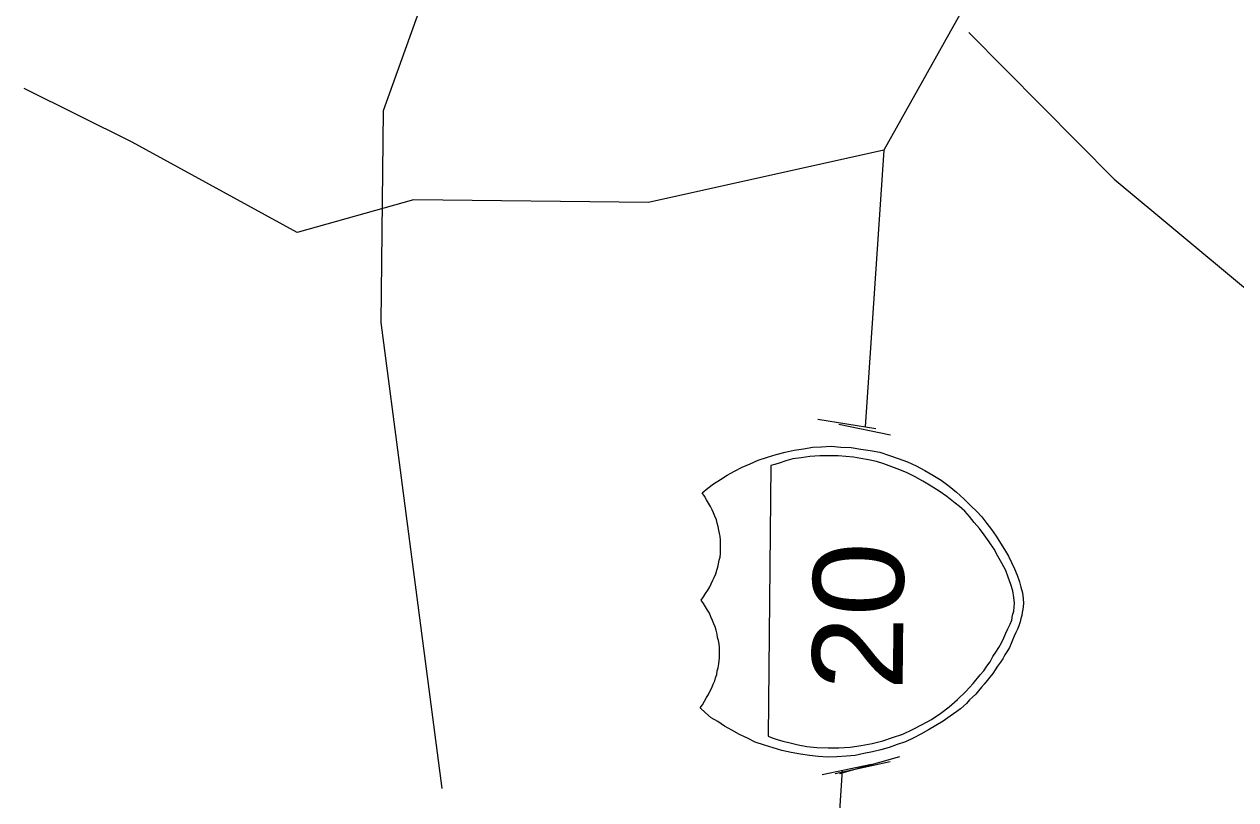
# Model space of a CAD drawing. Extents: x 2356576 to 2377878, y 6966390 to 6990634.
# Drawn here: x 2365922.2 to 2366013.1, y 6968773.4 to 6968831.6 of the extents above; entities that cross this region are included whole.
import ezdxf

# ---------------------------------------------------------------- set-up
doc = ezdxf.new("R2010")
doc.units = 0
doc.header["$LTSCALE"] = 7.1
doc.layers.add('19', color=7, linetype='Continuous', lineweight=13)
doc.layers.add('8', color=7, linetype='Continuous', lineweight=13)

msp = doc.modelspace()

# ---------------------------------------------------------------- linework, layer by layer
at = {"layer": '19', "lineweight": 25}
for p, q in [((2365930.315, 6968822.751), (2365922.224, 6968826.795)), ((2365986.716, 6968822.166), (2365985.329, 6968801.392))]:
    msp.add_line(p, q, dxfattribs=at)
at = {"layer": '19'}
for p, q in [((2365981.766, 6968801.969), (2365986.107, 6968801.264)), ((2365983.351, 6968801.592), (2365987.215, 6968800.8)), ((2365983.079, 6968775.402), (2365987.201, 6968776.287)), ((2365983.411, 6968775.398), (2365987.925, 6968776.671)), ((2365982.09, 6968775.32), (2365985.787, 6968776.094))]:
    msp.add_line(p, q, dxfattribs=at)
at = {"layer": '19', "lineweight": 25}
for points in [[(2365993.212, 6969055.404), (2365995.144, 6969044.943), (2365996.174, 6969031.612), (2365997.392, 6969012.874), (2365997.254, 6968999.555), (2365998.323, 6968990.003), (2366002.006, 6968983.305), (2366004.476, 6968969.926), (2366002.874, 6968951.222), (2366001.496, 6968934.107), (2366000.162, 6968915.368), (2366003.604, 6968885.811), (2365999.567, 6968857.919), (2365994.142, 6968835.442), (2365986.716, 6968822.166), (2365969.062, 6968818.241), (2365951.423, 6968818.424), (2365942.698, 6968815.994), (2365930.315, 6968822.751)], [(2365952.596, 6968844.725), (2365953.012, 6968835.868), (2365949.152, 6968825.108), (2365948.988, 6968809.237), (2365953.546, 6968774.267)], [(2365983.594, 6968775.636), (2365982.344, 6968756.568), (2365971.97, 6968737.143), (2365955.574, 6968726.78)]]:
    msp.add_lwpolyline(points, dxfattribs=at)
at = {"layer": '19'}
for points in [[(2365993.108, 6968830.981), (2366004.002, 6968819.979), (2366013.699, 6968811.898), (2366030.324, 6968794.501), (2366048.07, 6968778.809)], [(2365973.652, 6968789.388), (2365973.774, 6968789.627), (2365973.897, 6968789.897), (2365973.991, 6968790.105), (2365974.114, 6968790.375), (2365974.177, 6968790.643), (2365974.267, 6968790.882), (2365974.302, 6968791.121), (2365974.364, 6968791.393), (2365974.427, 6968791.632), (2365974.458, 6968791.9), (2365974.46, 6968792.14), (2365974.463, 6968792.412), (2365974.466, 6968792.652), (2365974.468, 6968792.892), (2365974.443, 6968793.192), (2365974.385, 6968793.401), (2365974.328, 6968793.641), (2365974.299, 6968793.914), (2365974.213, 6968794.182), (2365974.156, 6968794.423), (2365974.039, 6968794.696), (2365973.949, 6968794.937), (2365973.832, 6968795.178), (2365973.714, 6968795.42), (2365973.569, 6968795.661), (2365973.419, 6968795.935), (2365973.274, 6968796.204), (2365973.097, 6968796.446), (2365973.52, 6968796.802), (2365973.944, 6968797.129), (2365974.455, 6968797.452), (2365974.971, 6968797.779), (2365975.514, 6968798.073), (2365976.089, 6968798.367), (2365976.692, 6968798.629), (2365977.294, 6968798.895), (2365977.985, 6968799.128), (2365978.647, 6968799.329), (2365979.309, 6968799.502), (2365980.002, 6968799.647), (2365980.691, 6968799.76), (2365981.385, 6968799.872), (2365982.045, 6968799.894), (2365982.766, 6968799.946), (2365983.485, 6968799.879), (2365984.265, 6968799.843), (2365984.983, 6968799.715), (2365985.702, 6968799.616), (2365986.421, 6968799.488), (2365987.138, 6968799.241), (2365987.796, 6968799.026), (2365988.482, 6968798.779), (2365989.139, 6968798.472), (2365989.795, 6968798.133), (2365990.391, 6968797.767), (2365991.02, 6968797.401), (2365991.615, 6968796.946), (2365992.178, 6968796.488), (2365992.713, 6968796.003), (2365993.28, 6968795.457), (2365993.664, 6968795.061), (2365994.079, 6968794.637), (2365994.434, 6968794.153), (2365994.789, 6968793.701), (2365995.144, 6968793.186), (2365995.471, 6968792.674), (2365995.766, 6968792.191), (2365996.061, 6968791.708), (2365996.296, 6968791.226), (2365996.531, 6968790.743), (2365996.734, 6968790.261), (2365996.909, 6968789.779), (2365996.997, 6968789.358), (2365997.112, 6968788.937), (2365997.168, 6968788.516), (2365997.192, 6968788.156)], [(2365997.192, 6968788.156), (2365997.162, 6968787.916), (2365997.159, 6968787.704), (2365997.097, 6968787.465), (2365997.063, 6968787.257), (2365997, 6968787.018), (2365996.938, 6968786.779), (2365996.847, 6968786.48), (2365996.752, 6968786.209), (2365996.629, 6968785.97), (2365996.507, 6968785.703), (2365996.384, 6968785.404), (2365996.261, 6968785.134), (2365996.138, 6968784.835), (2365995.987, 6968784.596), (2365995.804, 6968784.298), (2365995.649, 6968784), (2365995.466, 6968783.734), (2365995.255, 6968783.436), (2365995.072, 6968783.166), (2365994.89, 6968782.9), (2365994.675, 6968782.63), (2365994.464, 6968782.364), (2365994.249, 6968782.094), (2365994.039, 6968781.856), (2365993.824, 6968781.591), (2365993.614, 6968781.353), (2365993.371, 6968781.115), (2365993.157, 6968780.905), (2365992.914, 6968780.64), (2365992.704, 6968780.43), (2365992.462, 6968780.253), (2365992.188, 6968780.047), (2365991.704, 6968779.692), (2365991.16, 6968779.306), (2365990.617, 6968778.984), (2365990.073, 6968778.657), (2365989.502, 6968778.335), (2365988.927, 6968778.041), (2365988.356, 6968777.775), (2365987.722, 6968777.574), (2365987.12, 6968777.34), (2365986.49, 6968777.166), (2365985.856, 6968777.021), (2365985.227, 6968776.879), (2365984.565, 6968776.734), (2365983.905, 6968776.681), (2365983.184, 6968776.629), (2365982.524, 6968776.607), (2365981.804, 6968776.675), (2365981.145, 6968776.742), (2365980.454, 6968776.837), (2365979.767, 6968776.964), (2365979.077, 6968777.123), (2365978.419, 6968777.31), (2365977.761, 6968777.525), (2365977.075, 6968777.744), (2365976.478, 6968778.05), (2365975.881, 6968778.324), (2365975.312, 6968778.63), (2365974.775, 6968778.936), (2365974.267, 6968779.301), (2365973.762, 6968779.578), (2365973.346, 6968779.943), (2365972.93, 6968780.307), (2365973.112, 6968780.545), (2365973.263, 6968780.812), (2365973.418, 6968781.082), (2365973.568, 6968781.32), (2365973.691, 6968781.587), (2365973.813, 6968781.826), (2365973.908, 6968782.097), (2365974.031, 6968782.336), (2365974.093, 6968782.575), (2365974.184, 6968782.814), (2365974.218, 6968783.082), (2365974.281, 6968783.321), (2365974.344, 6968783.621), (2365974.374, 6968783.832), (2365974.377, 6968784.072), (2365974.38, 6968784.372), (2365974.382, 6968784.612), (2365974.385, 6968784.852), (2365974.36, 6968785.12), (2365974.302, 6968785.361), (2365974.244, 6968785.602), (2365974.215, 6968785.842), (2365974.13, 6968786.143), (2365974.073, 6968786.383), (2365973.955, 6968786.625), (2365973.866, 6968786.866), (2365973.748, 6968787.139), (2365973.631, 6968787.408), (2365973.486, 6968787.65), (2365973.336, 6968787.891), (2365973.191, 6968788.133), (2365973.013, 6968788.407), (2365973.196, 6968788.645), (2365973.346, 6968788.883), (2365973.501, 6968789.15), (2365973.652, 6968789.388)]]:
    msp.add_lwpolyline(points, dxfattribs=at)
msp.add_lwpolyline([(2365978.25, 6968798.493), (2365978.04, 6968778.182), (2365978.339, 6968778.059), (2365978.725, 6968777.935), (2365979.144, 6968777.81), (2365979.683, 6968777.685), (2365980.281, 6968777.531), (2365980.94, 6968777.404), (2365981.691, 6968777.336), (2365982.531, 6968777.327), (2365983.339, 6968777.319), (2365984.18, 6968777.37), (2365985.021, 6968777.482), (2365985.835, 6968777.653), (2365986.645, 6968777.853), (2365987.367, 6968778.085), (2365988.15, 6968778.349), (2365988.874, 6968778.702), (2365989.597, 6968779.054), (2365990.293, 6968779.435), (2365990.986, 6968779.908), (2365991.623, 6968780.381), (2365992.257, 6968780.947), (2365992.863, 6968781.541), (2365993.41, 6968782.135), (2365993.956, 6968782.789), (2365994.231, 6968783.086), (2365994.443, 6968783.444), (2365994.687, 6968783.77), (2365994.903, 6968784.16), (2365995.114, 6968784.485), (2365995.358, 6968784.843), (2365995.541, 6968785.201), (2365995.725, 6968785.559), (2365995.881, 6968785.918), (2365996.032, 6968786.248), (2365996.188, 6968786.606), (2365996.311, 6968786.905), (2365996.375, 6968787.265), (2365996.466, 6968787.564), (2365996.501, 6968787.863), (2365996.532, 6968788.163), (2365996.477, 6968788.584), (2365996.394, 6968789.092), (2365996.247, 6968789.574), (2365996.044, 6968790.116), (2365995.87, 6968790.63), (2365995.575, 6968791.173), (2365995.281, 6968791.684), (2365994.986, 6968792.227), (2365994.632, 6968792.771), (2365994.245, 6968793.287), (2365993.89, 6968793.771), (2365993.507, 6968794.223), (2365993.152, 6968794.678), (2365992.796, 6968795.07), (2365992.407, 6968795.434), (2365992.082, 6968795.681), (2365991.455, 6968796.168), (2365990.859, 6968796.562), (2365990.263, 6968796.96), (2365989.639, 6968797.327), (2365989.07, 6968797.661), (2365988.473, 6968797.939), (2365987.908, 6968798.185), (2365987.31, 6968798.399), (2365986.712, 6968798.617), (2365986.174, 6968798.803), (2365985.575, 6968798.929), (2365985.004, 6968799.023), (2365984.437, 6968799.121), (2365983.866, 6968799.187), (2365983.298, 6968799.221), (2365982.758, 6968799.226), (2365981.918, 6968799.235), (2365981.166, 6968799.183), (2365980.504, 6968799.07), (2365979.903, 6968798.988), (2365979.362, 6968798.841), (2365978.94, 6968798.698), (2365978.551, 6968798.582)], close=True, dxfattribs=at)
at = {"layer": '8', "lineweight": 25}
for p, q in [((2365930.315, 6968822.751), (2365922.224, 6968826.795)), ((2365986.716, 6968822.166), (2365985.329, 6968801.392))]:
    msp.add_line(p, q, dxfattribs=at)
at = {"layer": '8'}
for p, q in [((2365981.766, 6968801.969), (2365986.107, 6968801.264)), ((2365983.351, 6968801.592), (2365987.215, 6968800.8)), ((2365983.079, 6968775.402), (2365987.201, 6968776.287)), ((2365983.411, 6968775.398), (2365987.925, 6968776.671)), ((2365982.09, 6968775.32), (2365985.787, 6968776.094))]:
    msp.add_line(p, q, dxfattribs=at)
at = {"layer": '8', "lineweight": 25}
for points in [[(2365993.212, 6969055.404), (2365995.144, 6969044.943), (2365996.174, 6969031.612), (2365997.392, 6969012.874), (2365997.254, 6968999.555), (2365998.323, 6968990.003), (2366002.006, 6968983.305), (2366004.476, 6968969.926), (2366002.874, 6968951.222), (2366001.496, 6968934.107), (2366000.162, 6968915.368), (2366003.604, 6968885.811), (2365999.567, 6968857.919), (2365994.142, 6968835.442), (2365986.716, 6968822.166), (2365969.062, 6968818.241), (2365951.423, 6968818.424), (2365942.698, 6968815.994), (2365930.315, 6968822.751)], [(2365952.596, 6968844.725), (2365953.012, 6968835.868), (2365949.152, 6968825.108), (2365948.988, 6968809.237), (2365953.546, 6968774.267)], [(2365983.594, 6968775.636), (2365982.344, 6968756.568), (2365971.97, 6968737.143), (2365955.574, 6968726.78)]]:
    msp.add_lwpolyline(points, dxfattribs=at)
at = {"layer": '8'}
for points in [[(2365993.108, 6968830.981), (2366004.002, 6968819.979), (2366013.699, 6968811.898), (2366030.324, 6968794.501), (2366048.07, 6968778.809)], [(2365973.652, 6968789.388), (2365973.774, 6968789.627), (2365973.897, 6968789.897), (2365973.991, 6968790.105), (2365974.114, 6968790.375), (2365974.177, 6968790.643), (2365974.267, 6968790.882), (2365974.302, 6968791.121), (2365974.364, 6968791.393), (2365974.427, 6968791.632), (2365974.458, 6968791.9), (2365974.46, 6968792.14), (2365974.463, 6968792.412), (2365974.466, 6968792.652), (2365974.468, 6968792.892), (2365974.443, 6968793.192), (2365974.385, 6968793.401), (2365974.328, 6968793.641), (2365974.299, 6968793.914), (2365974.213, 6968794.182), (2365974.156, 6968794.423), (2365974.039, 6968794.696), (2365973.949, 6968794.937), (2365973.832, 6968795.178), (2365973.714, 6968795.42), (2365973.569, 6968795.661), (2365973.419, 6968795.935), (2365973.274, 6968796.204), (2365973.097, 6968796.446), (2365973.52, 6968796.802), (2365973.944, 6968797.129), (2365974.455, 6968797.452), (2365974.971, 6968797.779), (2365975.514, 6968798.073), (2365976.089, 6968798.367), (2365976.692, 6968798.629), (2365977.294, 6968798.895), (2365977.985, 6968799.128), (2365978.647, 6968799.329), (2365979.309, 6968799.502), (2365980.002, 6968799.647), (2365980.691, 6968799.76), (2365981.385, 6968799.872), (2365982.045, 6968799.894), (2365982.766, 6968799.946), (2365983.485, 6968799.879), (2365984.265, 6968799.843), (2365984.983, 6968799.715), (2365985.702, 6968799.616), (2365986.421, 6968799.488), (2365987.138, 6968799.241), (2365987.796, 6968799.026), (2365988.482, 6968798.779), (2365989.139, 6968798.472), (2365989.795, 6968798.133), (2365990.391, 6968797.767), (2365991.02, 6968797.401), (2365991.615, 6968796.946), (2365992.178, 6968796.488), (2365992.713, 6968796.003), (2365993.28, 6968795.457), (2365993.664, 6968795.061), (2365994.079, 6968794.637), (2365994.434, 6968794.153), (2365994.789, 6968793.701), (2365995.144, 6968793.186), (2365995.471, 6968792.674), (2365995.766, 6968792.191), (2365996.061, 6968791.708), (2365996.296, 6968791.226), (2365996.531, 6968790.743), (2365996.734, 6968790.261), (2365996.909, 6968789.779), (2365996.997, 6968789.358), (2365997.112, 6968788.937), (2365997.168, 6968788.516), (2365997.192, 6968788.156)], [(2365997.192, 6968788.156), (2365997.162, 6968787.916), (2365997.159, 6968787.704), (2365997.097, 6968787.465), (2365997.063, 6968787.257), (2365997, 6968787.018), (2365996.938, 6968786.779), (2365996.847, 6968786.48), (2365996.752, 6968786.209), (2365996.629, 6968785.97), (2365996.507, 6968785.703), (2365996.384, 6968785.404), (2365996.261, 6968785.134), (2365996.138, 6968784.835), (2365995.987, 6968784.596), (2365995.804, 6968784.298), (2365995.649, 6968784), (2365995.466, 6968783.734), (2365995.255, 6968783.436), (2365995.072, 6968783.166), (2365994.89, 6968782.9), (2365994.675, 6968782.63), (2365994.464, 6968782.364), (2365994.249, 6968782.094), (2365994.039, 6968781.856), (2365993.824, 6968781.591), (2365993.614, 6968781.353), (2365993.371, 6968781.115), (2365993.157, 6968780.905), (2365992.914, 6968780.64), (2365992.704, 6968780.43), (2365992.462, 6968780.253), (2365992.188, 6968780.047), (2365991.704, 6968779.692), (2365991.16, 6968779.306), (2365990.617, 6968778.984), (2365990.073, 6968778.657), (2365989.502, 6968778.335), (2365988.927, 6968778.041), (2365988.356, 6968777.775), (2365987.722, 6968777.574), (2365987.12, 6968777.34), (2365986.49, 6968777.166), (2365985.856, 6968777.021), (2365985.227, 6968776.879), (2365984.565, 6968776.734), (2365983.905, 6968776.681), (2365983.184, 6968776.629), (2365982.524, 6968776.607), (2365981.804, 6968776.675), (2365981.145, 6968776.742), (2365980.454, 6968776.837), (2365979.767, 6968776.964), (2365979.077, 6968777.123), (2365978.419, 6968777.31), (2365977.761, 6968777.525), (2365977.075, 6968777.744), (2365976.478, 6968778.05), (2365975.881, 6968778.324), (2365975.312, 6968778.63), (2365974.775, 6968778.936), (2365974.267, 6968779.301), (2365973.762, 6968779.578), (2365973.346, 6968779.943), (2365972.93, 6968780.307), (2365973.112, 6968780.545), (2365973.263, 6968780.812), (2365973.418, 6968781.082), (2365973.568, 6968781.32), (2365973.691, 6968781.587), (2365973.813, 6968781.826), (2365973.908, 6968782.097), (2365974.031, 6968782.336), (2365974.093, 6968782.575), (2365974.184, 6968782.814), (2365974.218, 6968783.082), (2365974.281, 6968783.321), (2365974.344, 6968783.621), (2365974.374, 6968783.832), (2365974.377, 6968784.072), (2365974.38, 6968784.372), (2365974.382, 6968784.612), (2365974.385, 6968784.852), (2365974.36, 6968785.12), (2365974.302, 6968785.361), (2365974.244, 6968785.602), (2365974.215, 6968785.842), (2365974.13, 6968786.143), (2365974.073, 6968786.383), (2365973.955, 6968786.625), (2365973.866, 6968786.866), (2365973.748, 6968787.139), (2365973.631, 6968787.408), (2365973.486, 6968787.65), (2365973.336, 6968787.891), (2365973.191, 6968788.133), (2365973.013, 6968788.407), (2365973.196, 6968788.645), (2365973.346, 6968788.883), (2365973.501, 6968789.15), (2365973.652, 6968789.388)]]:
    msp.add_lwpolyline(points, dxfattribs=at)
msp.add_lwpolyline([(2365978.25, 6968798.493), (2365978.04, 6968778.182), (2365978.339, 6968778.059), (2365978.725, 6968777.935), (2365979.144, 6968777.81), (2365979.683, 6968777.685), (2365980.281, 6968777.531), (2365980.94, 6968777.404), (2365981.691, 6968777.336), (2365982.531, 6968777.327), (2365983.339, 6968777.319), (2365984.18, 6968777.37), (2365985.021, 6968777.482), (2365985.835, 6968777.653), (2365986.645, 6968777.853), (2365987.367, 6968778.085), (2365988.15, 6968778.349), (2365988.874, 6968778.702), (2365989.597, 6968779.054), (2365990.293, 6968779.435), (2365990.986, 6968779.908), (2365991.623, 6968780.381), (2365992.257, 6968780.947), (2365992.863, 6968781.541), (2365993.41, 6968782.135), (2365993.956, 6968782.789), (2365994.231, 6968783.086), (2365994.443, 6968783.444), (2365994.687, 6968783.77), (2365994.903, 6968784.16), (2365995.114, 6968784.485), (2365995.358, 6968784.843), (2365995.541, 6968785.201), (2365995.725, 6968785.559), (2365995.881, 6968785.918), (2365996.032, 6968786.248), (2365996.188, 6968786.606), (2365996.311, 6968786.905), (2365996.375, 6968787.265), (2365996.466, 6968787.564), (2365996.501, 6968787.863), (2365996.532, 6968788.163), (2365996.477, 6968788.584), (2365996.394, 6968789.092), (2365996.247, 6968789.574), (2365996.044, 6968790.116), (2365995.87, 6968790.63), (2365995.575, 6968791.173), (2365995.281, 6968791.684), (2365994.986, 6968792.227), (2365994.632, 6968792.771), (2365994.245, 6968793.287), (2365993.89, 6968793.771), (2365993.507, 6968794.223), (2365993.152, 6968794.678), (2365992.796, 6968795.07), (2365992.407, 6968795.434), (2365992.082, 6968795.681), (2365991.455, 6968796.168), (2365990.859, 6968796.562), (2365990.263, 6968796.96), (2365989.639, 6968797.327), (2365989.07, 6968797.661), (2365988.473, 6968797.939), (2365987.908, 6968798.185), (2365987.31, 6968798.399), (2365986.712, 6968798.617), (2365986.174, 6968798.803), (2365985.575, 6968798.929), (2365985.004, 6968799.023), (2365984.437, 6968799.121), (2365983.866, 6968799.187), (2365983.298, 6968799.221), (2365982.758, 6968799.226), (2365981.918, 6968799.235), (2365981.166, 6968799.183), (2365980.504, 6968799.07), (2365979.903, 6968798.988), (2365979.362, 6968798.841), (2365978.94, 6968798.698), (2365978.551, 6968798.582)], close=True, dxfattribs=at)

# ---------------------------------------------------------------- texts
at = {"layer": '19', "width": 1.1}
msp.add_text('20', height=6.798, rotation=89.406, dxfattribs=at).set_placement((2365988.124, 6968781.59))
at = {"layer": '8', "width": 1.1}
msp.add_text('20', height=6.798, rotation=89.406, dxfattribs=at).set_placement((2365988.124, 6968781.59))

doc.saveas('drawing.dxf')
